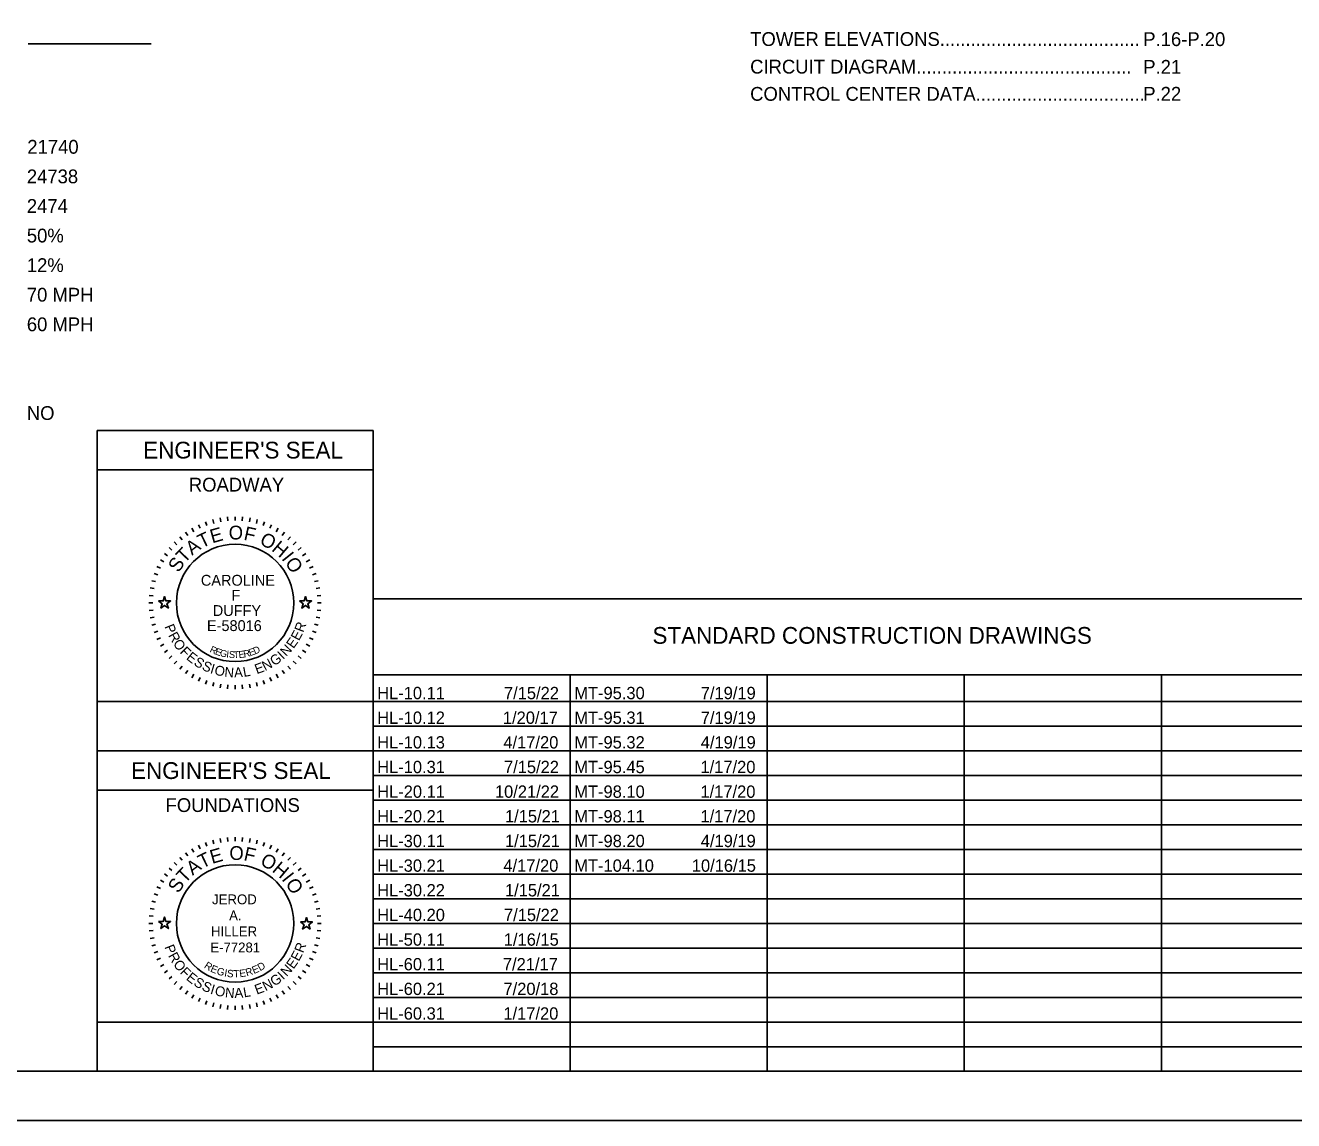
# Model space of a CAD drawing. Extents: x 0 to 34, y 0 to 22.
# Drawn here: x 7.72 to 20.59, y 0 to 11.11 of the extents above; entities that cross this region are included whole.
import ezdxf

# ---------------------------------------------------------------- set-up
doc = ezdxf.new("R2010")
doc.units = 0
for name, color, linetype in [('Default', 7, 'Continuous'), ('SH_Border', 7, 'Continuous'), ('SH_Cut_Line', 7, 'Continuous'), ('SH_Data', 7, 'Continuous'), ('SH_Text', 7, 'Continuous')]:
    doc.layers.add(name, color=color, linetype=linetype)

msp = doc.modelspace()

# ---------------------------------------------------------------- linework, layer by layer
at = {"layer": 'Default'}
for points in [[(9.074, 5.27), (9.121, 5.27), (9.135, 5.315), (9.149, 5.27), (9.196, 5.27), (9.158, 5.242), (9.173, 5.198), (9.135, 5.225), (9.097, 5.198), (9.112, 5.242)], [(10.504, 5.27), (10.551, 5.27), (10.565, 5.315), (10.579, 5.27), (10.626, 5.27), (10.588, 5.242), (10.603, 5.198), (10.565, 5.225), (10.527, 5.198), (10.542, 5.242)]]:
    msp.add_lwpolyline(points, close=True, dxfattribs=at)
at = {"layer": 'SH_Border'}
msp.add_lwpolyline([(1.5, 21.5), (33.5, 21.5), (33.5, 0.5), (1.5, 0.5)], close=True, dxfattribs=at)
at = {"layer": 'SH_Cut_Line'}
msp.add_lwpolyline([(0, 0), (34, 0), (34, 22), (0, 22)], close=True, dxfattribs=at)
at = {"layer": 'SH_Data'}
for p, q in [((9, 10.922), (7.75, 10.922)), ((8.45, 3.75), (8.45, 7)), ((8.45, 7), (11.25, 7)), ((11.25, 7), (11.25, 3.75)), ((8.45, 6.6), (11.25, 6.6)), ((9.551, 6.072), (9.564, 6.035)), ((9.624, 6.095), (9.634, 6.057)), ((9.698, 6.112), (9.705, 6.072)), ((9.774, 6.122), (9.777, 6.082)), ((9.85, 6.125), (9.85, 6.085)), ((9.926, 6.122), (9.923, 6.082)), ((10.002, 6.112), (9.995, 6.072)), ((10.076, 6.095), (10.066, 6.057)), ((10.149, 6.072), (10.136, 6.035)), ((9.288, 5.92), (9.313, 5.89)), ((9.348, 5.967), (9.371, 5.934)), ((9.413, 6.008), (9.433, 5.973)), ((9.48, 6.043), (9.497, 6.007)), ((10.22, 6.043), (10.203, 6.007)), ((10.287, 6.008), (10.267, 5.973)), ((10.352, 5.967), (10.329, 5.934)), ((10.412, 5.92), (10.387, 5.89)), ((9.18, 5.812), (9.21, 5.787)), ((9.231, 5.869), (9.26, 5.84)), ((10.469, 5.869), (10.44, 5.84)), ((10.52, 5.812), (10.49, 5.787)), ((9.092, 5.688), (9.127, 5.668)), ((9.133, 5.752), (9.166, 5.729)), ((10.567, 5.752), (10.534, 5.729)), ((10.608, 5.688), (10.573, 5.668)), ((9.028, 5.549), (9.065, 5.536)), ((9.057, 5.62), (9.093, 5.603)), ((10.643, 5.62), (10.607, 5.603)), ((10.672, 5.549), (10.635, 5.536)), ((9.005, 5.476), (9.043, 5.466)), ((10.695, 5.476), (10.657, 5.466)), ((8.978, 5.326), (9.018, 5.323)), ((8.988, 5.402), (9.028, 5.395)), ((10.712, 5.402), (10.672, 5.395)), ((10.722, 5.326), (10.682, 5.323)), ((11.25, 5.292), (24.7, 5.292)), ((11.25, 0.5), (11.25, 5.292)), ((11.25, 0.5), (11.25, 5.292)), ((8.975, 5.25), (9.015, 5.25)), ((8.978, 5.174), (9.018, 5.177)), ((10.722, 5.174), (10.682, 5.177)), ((10.725, 5.25), (10.685, 5.25)), ((8.988, 5.098), (9.028, 5.105)), ((9.005, 5.024), (9.043, 5.034)), ((10.695, 5.024), (10.657, 5.034)), ((10.712, 5.098), (10.672, 5.105)), ((9.028, 4.951), (9.065, 4.964)), ((9.057, 4.88), (9.093, 4.897)), ((10.643, 4.88), (10.607, 4.897)), ((10.672, 4.951), (10.635, 4.964)), ((9.092, 4.813), (9.127, 4.833)), ((9.133, 4.748), (9.166, 4.771)), ((10.567, 4.748), (10.534, 4.771)), ((10.608, 4.813), (10.573, 4.833)), ((9.18, 4.688), (9.21, 4.713)), ((9.231, 4.631), (9.26, 4.66)), ((10.469, 4.631), (10.44, 4.66)), ((10.52, 4.688), (10.49, 4.713)), ((9.288, 4.58), (9.313, 4.61)), ((9.348, 4.533), (9.371, 4.566)), ((9.413, 4.492), (9.433, 4.527)), ((10.287, 4.492), (10.267, 4.527)), ((10.352, 4.533), (10.329, 4.566)), ((10.412, 4.58), (10.387, 4.61)), ((11.25, 4.521), (24.7, 4.521)), ((13.25, 0.5), (13.25, 4.521)), ((15.25, 0.5), (15.25, 4.521)), ((17.25, 0.5), (17.25, 4.521)), ((19.25, 0.5), (19.25, 4.521)), ((9.48, 4.457), (9.497, 4.493)), ((9.551, 4.428), (9.564, 4.465)), ((9.624, 4.405), (9.634, 4.443)), ((9.698, 4.388), (9.705, 4.428)), ((9.774, 4.378), (9.777, 4.418)), ((9.85, 4.375), (9.85, 4.415)), ((9.926, 4.378), (9.923, 4.418)), ((10.002, 4.388), (9.995, 4.428)), ((10.076, 4.405), (10.066, 4.443)), ((10.149, 4.428), (10.136, 4.465)), ((10.22, 4.457), (10.203, 4.493)), ((11.25, 4.25), (24.7, 4.25)), ((11.25, 4), (24.7, 4)), ((11.25, 3.75), (8.45, 3.75)), ((8.45, 3.75), (8.45, 0.5)), ((11.25, 3.75), (8.45, 3.75)), ((8.45, 3.75), (11.25, 3.75)), ((11.25, 3.75), (24.7, 3.75)), ((11.25, 0.5), (11.25, 3.75)), ((11.25, 3.5), (24.7, 3.5)), ((11.25, 3.35), (8.45, 3.35)), ((11.25, 3.25), (24.7, 3.25)), ((11.25, 3), (24.7, 3)), ((9.624, 2.845), (9.634, 2.807)), ((9.698, 2.862), (9.705, 2.822)), ((9.774, 2.872), (9.777, 2.832)), ((9.85, 2.875), (9.85, 2.835)), ((9.926, 2.872), (9.923, 2.832)), ((10.002, 2.862), (9.995, 2.822)), ((10.076, 2.845), (10.066, 2.807)), ((9.348, 2.717), (9.371, 2.684)), ((9.413, 2.758), (9.433, 2.723)), ((9.48, 2.793), (9.497, 2.757)), ((9.551, 2.822), (9.564, 2.785)), ((10.149, 2.822), (10.136, 2.785)), ((10.22, 2.793), (10.203, 2.757)), ((10.287, 2.758), (10.267, 2.723)), ((10.352, 2.717), (10.329, 2.684)), ((11.25, 2.75), (24.7, 2.75)), ((9.231, 2.619), (9.26, 2.59)), ((9.288, 2.67), (9.313, 2.64)), ((10.412, 2.67), (10.387, 2.64)), ((10.469, 2.619), (10.44, 2.59)), ((9.133, 2.502), (9.166, 2.479)), ((9.18, 2.562), (9.21, 2.537)), ((10.52, 2.562), (10.49, 2.537)), ((10.567, 2.502), (10.534, 2.479)), ((11.25, 2.5), (24.7, 2.5)), ((9.057, 2.37), (9.093, 2.353)), ((9.092, 2.438), (9.127, 2.418)), ((10.608, 2.438), (10.573, 2.418)), ((10.643, 2.37), (10.607, 2.353)), ((9.005, 2.226), (9.043, 2.216)), ((9.028, 2.299), (9.065, 2.286)), ((10.672, 2.299), (10.635, 2.286)), ((10.695, 2.226), (10.657, 2.216)), ((11.25, 2.25), (24.7, 2.25)), ((8.978, 2.076), (9.018, 2.073)), ((8.988, 2.152), (9.028, 2.145)), ((10.712, 2.152), (10.672, 2.145)), ((10.722, 2.076), (10.682, 2.073)), ((8.975, 2), (9.015, 2)), ((10.725, 2), (10.685, 2)), ((11.25, 2), (24.7, 2)), ((8.978, 1.924), (9.018, 1.927)), ((8.988, 1.848), (9.028, 1.855)), ((10.712, 1.848), (10.672, 1.855)), ((10.722, 1.924), (10.682, 1.927)), ((9.005, 1.774), (9.043, 1.784)), ((9.028, 1.701), (9.065, 1.714)), ((10.672, 1.701), (10.635, 1.714)), ((10.695, 1.774), (10.657, 1.784)), ((11.25, 1.75), (24.7, 1.75)), ((9.057, 1.63), (9.093, 1.647)), ((9.092, 1.563), (9.127, 1.583)), ((10.608, 1.563), (10.573, 1.583)), ((10.643, 1.63), (10.607, 1.647)), ((9.133, 1.498), (9.166, 1.521)), ((9.18, 1.438), (9.21, 1.463)), ((10.52, 1.438), (10.49, 1.463)), ((10.567, 1.498), (10.534, 1.521)), ((11.25, 1.5), (24.7, 1.5)), ((9.231, 1.381), (9.26, 1.41)), ((9.288, 1.33), (9.313, 1.36)), ((9.348, 1.283), (9.371, 1.316)), ((10.352, 1.283), (10.329, 1.316)), ((10.412, 1.33), (10.387, 1.36)), ((10.469, 1.381), (10.44, 1.41)), ((9.413, 1.242), (9.433, 1.277)), ((9.48, 1.207), (9.497, 1.243)), ((9.551, 1.178), (9.564, 1.215)), ((9.624, 1.155), (9.634, 1.193)), ((9.698, 1.138), (9.705, 1.178)), ((9.774, 1.128), (9.777, 1.168)), ((9.85, 1.125), (9.85, 1.165)), ((9.926, 1.128), (9.923, 1.168)), ((10.002, 1.138), (9.995, 1.178)), ((10.076, 1.155), (10.066, 1.193)), ((10.149, 1.178), (10.136, 1.215)), ((10.22, 1.207), (10.203, 1.243)), ((10.287, 1.242), (10.267, 1.277)), ((11.25, 1.25), (24.7, 1.25)), ((11.25, 1), (24.7, 1)), ((11.25, 0.75), (24.7, 0.75)), ((11.25, 0.5), (8.45, 0.5))]:
    msp.add_line(p, q, dxfattribs=at)
for points in [[(8.45, 3.75), (8.45, 4.25), (11.25, 4.25), (11.25, 3.75)], [(9.074, 2.02), (9.121, 2.02), (9.135, 2.065), (9.149, 2.02), (9.196, 2.02), (9.158, 1.992), (9.173, 1.948), (9.135, 1.975), (9.097, 1.948), (9.112, 1.992)], [(10.513, 2.015), (10.56, 2.015), (10.574, 2.059), (10.589, 2.015), (10.635, 2.015), (10.598, 1.987), (10.612, 1.942), (10.574, 1.97), (10.536, 1.942), (10.551, 1.987)], [(11.25, 0.5), (11.25, 1), (8.45, 1), (8.45, 0.5)]]:
    msp.add_lwpolyline(points, close=True, dxfattribs=at)
for centre in [(9.85, 5.25), (9.85, 2)]:
    msp.add_circle(centre, 0.595, dxfattribs=at)

# ---------------------------------------------------------------- texts
for s, height, p in [('TOWER ELEVATIONS.......................................', 0.14, (15.077, 10.899)), ('P.16-P.20', 0.14, (19.066, 10.898)), ('CIRCUIT DIAGRAM..........................................', 0.14, (15.077, 10.619)), ('P.21', 0.14, (19.066, 10.617)), ('CONTROL CENTER DATA.................................', 0.14, (15.077, 10.343)), ('P.22', 0.14, (19.066, 10.344)), ('21740', 0.14, (7.742, 9.806)), ('24738', 0.14, (7.737, 9.506)), ('2474', 0.14, (7.737, 9.206)), ('50%', 0.14, (7.737, 8.906)), ('12%', 0.14, (7.737, 8.606)), ('70 MPH', 0.14, (7.737, 8.306)), ('60 MPH', 0.14, (7.737, 8.006)), ("ENGINEER'S SEAL", 0.17, (8.918, 6.715)), ('ROADWAY', 0.14, (9.381, 6.38)), ('CAROLINE', 0.11, (9.503, 5.425)), ('F', 0.11, (9.814, 5.272)), ('DUFFY', 0.11, (9.624, 5.118)), ('E-58016', 0.11, (9.565, 4.965)), ('STANDARD CONSTRUCTION DRAWINGS', 0.17, (14.086, 4.836)), ("ENGINEER'S SEAL", 0.17, (8.795, 3.465)), ('FOUNDATIONS', 0.14, (9.145, 3.13)), ('JEROD', 0.1, (9.617, 2.194)), ('A.', 0.1, (9.79, 2.031)), ('HILLER', 0.1, (9.606, 1.869)), ('E-77281', 0.1, (9.599, 1.706))]:
    msp.add_text(s, height=height, dxfattribs=at).set_placement(p)
for s, height, rotation, p in [('T', 0.14, 25.7167, (9.512, 5.802)), ('E', 0.14, 15.7571, (9.618, 5.854)), ('O', 0.14, 359.7812, (9.785, 5.894)), ('F', 0.14, 347.4362, (9.931, 5.892)), ('O', 0.14, 332.2586, (10.09, 5.852)), ('T', 0.14, 46.4344, (9.338, 5.646)), ('A', 0.14, 36.4747, (9.413, 5.728)), ('H', 0.14, 319.9136, (10.213, 5.786)), ('S', 0.14, 57.1924, (9.278, 5.551)), ('I', 0.14, 308.367, (10.316, 5.698)), ('O', 0.14, 303.1491, (10.352, 5.659)), ('P', 0.1, 291.494, (9.132, 5.012)), ('R', 0.1, 69.2322, (10.542, 4.945)), ('R', 0.1, 298.7311, (9.169, 4.922)), ('E', 0.1, 54.758, (10.443, 4.781)), ('E', 0.1, 61.9951, (10.498, 4.86)), ('O', 0.1, 306.4666, (9.215, 4.838)), ('F', 0.1, 314.7068, (9.284, 4.748)), ('R', 0.07, 334.487, (9.587, 4.755)), ('E', 0.07, 341.04, (9.641, 4.73)), ('G', 0.07, 347.4752, (9.691, 4.712)), ('I', 0.07, 353.7858, (9.759, 4.697)), ('S', 0.07, 356.8926, (9.786, 4.693)), ('E', 0.07, 6.0117, (9.889, 4.691)), ('R', 0.07, 11.9184, (9.942, 4.697)), ('E', 0.07, 17.6836, (10, 4.71)), ('D', 0.07, 23.3052, (10.051, 4.727)), ('N', 0.1, 47.0224, (10.37, 4.701)), ('E', 0.1, 321.4393, (9.348, 4.685)), ('S', 0.1, 328.6764, (9.424, 4.625)), ('S', 0.1, 335.9134, (9.506, 4.577)), ('T', 0.07, 3.0061, (9.836, 4.689)), ('E', 0.1, 20.0742, (10.071, 4.527)), ('N', 0.1, 27.3113, (10.154, 4.558)), ('G', 0.1, 35.0469, (10.248, 4.607)), ('I', 0.1, 43.287, (10.337, 4.671)), ('I', 0.1, 343.1505, (9.591, 4.54)), ('O', 0.1, 346.8859, (9.634, 4.525)), ('N', 0.1, 355.1261, (9.739, 4.502)), ('A', 0.1, 2.8617, (9.842, 4.494)), ('L', 0.1, 10.0987, (9.939, 4.499)), ('T', 0.14, 25.7167, (9.516, 2.554)), ('E', 0.14, 15.7571, (9.617, 2.603)), ('O', 0.14, 359.7812, (9.792, 2.644)), ('F', 0.14, 347.4362, (9.931, 2.642)), ('O', 0.14, 332.2586, (10.096, 2.598)), ('T', 0.14, 46.4344, (9.342, 2.4)), ('A', 0.14, 36.4747, (9.419, 2.482)), ('H', 0.14, 319.9136, (10.218, 2.532)), ('S', 0.14, 57.1924, (9.276, 2.298)), ('I', 0.14, 308.367, (10.317, 2.447)), ('O', 0.14, 303.1491, (10.356, 2.403)), ('R', 0.1, 69.2322, (10.541, 1.694)), ('P', 0.1, 291.494, (9.132, 1.762)), ('R', 0.1, 298.7311, (9.168, 1.673)), ('E', 0.1, 61.9951, (10.497, 1.609)), ('O', 0.1, 306.4666, (9.218, 1.585)), ('F', 0.1, 314.7068, (9.284, 1.498)), ('R', 0.075, 327.8239, (9.53, 1.554)), ('E', 0.075, 337.7777, (9.594, 1.513)), ('G', 0.075, 344.2727, (9.658, 1.485)), ('R', 0.075, 17.6836, (9.969, 1.463)), ('E', 0.075, 23.3052, (10.041, 1.486)), ('D', 0.075, 31.466, (10.105, 1.514)), ('N', 0.1, 47.0224, (10.374, 1.455)), ('E', 0.1, 54.758, (10.443, 1.531)), ('E', 0.1, 321.4393, (9.347, 1.435)), ('S', 0.1, 328.6764, (9.422, 1.377)), ('I', 0.075, 350.6464, (9.737, 1.463)), ('S', 0.075, 353.7858, (9.765, 1.458)), ('T', 0.075, 3.0061, (9.835, 1.451)), ('E', 0.075, 8.9826, (9.899, 1.453)), ('N', 0.1, 27.3113, (10.16, 1.31)), ('G', 0.1, 35.0469, (10.25, 1.358)), ('I', 0.1, 43.287, (10.338, 1.422)), ('S', 0.1, 335.9134, (9.504, 1.328)), ('I', 0.1, 343.1505, (9.592, 1.289)), ('O', 0.1, 346.8859, (9.638, 1.274)), ('N', 0.1, 355.1261, (9.745, 1.251)), ('A', 0.1, 2.8617, (9.846, 1.244)), ('L', 0.1, 10.0987, (9.942, 1.249)), ('E', 0.1, 20.0742, (10.07, 1.277))]:
    msp.add_text(s, height=height, rotation=rotation, dxfattribs=at).set_placement(p)
at = {"layer": 'SH_Text'}
for s, height, p in [('NO', 0.14, (7.737, 7.106)), ('HL-10.11', 0.125, (11.292, 4.274)), ('7/15/22', 0.125, (12.579, 4.274)), ('MT-95.30', 0.125, (13.292, 4.274)), ('7/19/19', 0.125, (14.576, 4.274)), ('HL-10.12', 0.125, (11.292, 4.024)), ('1/20/17', 0.125, (12.568, 4.024)), ('MT-95.31', 0.125, (13.292, 4.024)), ('7/19/19', 0.125, (14.576, 4.024)), ('HL-10.13', 0.125, (11.292, 3.774)), ('4/17/20', 0.125, (12.573, 3.774)), ('MT-95.32', 0.125, (13.292, 3.774)), ('4/19/19', 0.125, (14.576, 3.774)), ('HL-10.31', 0.125, (11.292, 3.524)), ('7/15/22', 0.125, (12.579, 3.524)), ('MT-95.45', 0.125, (13.292, 3.524)), ('1/17/20', 0.125, (14.573, 3.524)), ('HL-20.11', 0.125, (11.292, 3.274)), ('10/21/22', 0.125, (12.487, 3.274)), ('MT-98.10', 0.125, (13.292, 3.274)), ('1/17/20', 0.125, (14.573, 3.274)), ('HL-20.21', 0.125, (11.292, 3.024)), ('1/15/21', 0.125, (12.589, 3.024)), ('MT-98.11', 0.125, (13.292, 3.024)), ('1/17/20', 0.125, (14.573, 3.024)), ('HL-30.11', 0.125, (11.292, 2.774)), ('1/15/21', 0.125, (12.589, 2.774)), ('MT-98.20', 0.125, (13.292, 2.774)), ('4/19/19', 0.125, (14.576, 2.774)), ('HL-30.21', 0.125, (11.292, 2.524)), ('4/17/20', 0.125, (12.573, 2.524)), ('MT-104.10', 0.125, (13.292, 2.524)), ('10/16/15', 0.125, (14.485, 2.524)), ('HL-30.22', 0.125, (11.292, 2.274)), ('1/15/21', 0.125, (12.589, 2.274)), ('HL-40.20', 0.125, (11.292, 2.024)), ('7/15/22', 0.125, (12.579, 2.024)), ('HL-50.11', 0.125, (11.292, 1.774)), ('1/16/15', 0.125, (12.577, 1.774)), ('HL-60.11', 0.125, (11.292, 1.524)), ('7/21/17', 0.125, (12.568, 1.524)), ('HL-60.21', 0.125, (11.292, 1.274)), ('7/20/18', 0.125, (12.574, 1.274)), ('HL-60.31', 0.125, (11.292, 1.024)), ('1/17/20', 0.125, (12.573, 1.024))]:
    msp.add_text(s, height=height, dxfattribs=at).set_placement(p)

doc.saveas('drawing.dxf')
